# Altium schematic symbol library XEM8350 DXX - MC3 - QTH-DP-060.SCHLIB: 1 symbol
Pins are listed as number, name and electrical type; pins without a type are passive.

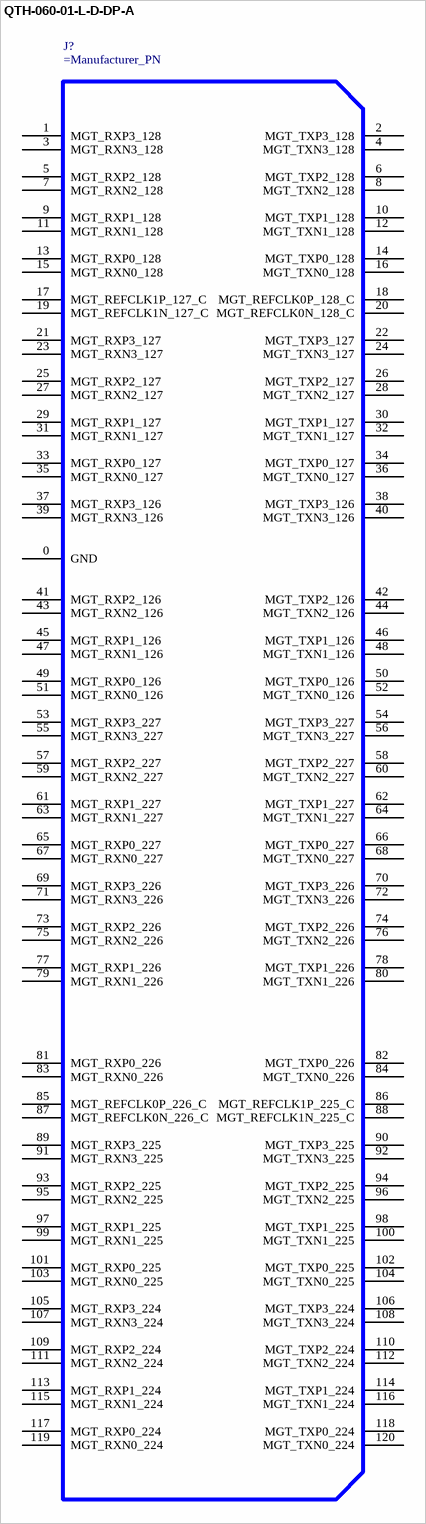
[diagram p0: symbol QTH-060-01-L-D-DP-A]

## QTH-060-01-L-D-DP-A
designator J?
pins: 0 GND, 1 MGT_RXP3_128, 2 MGT_TXP3_128, 3 MGT_RXN3_128, 4 MGT_TXN3_128, 5 MGT_RXP2_128, 6 MGT_TXP2_128, 7 MGT_RXN2_128, 8 MGT_TXN2_128, 9 MGT_RXP1_128, 10 MGT_TXP1_128, 11 MGT_RXN1_128, 12 MGT_TXN1_128, 13 MGT_RXP0_128, 14 MGT_TXP0_128, 15 MGT_RXN0_128, 16 MGT_TXN0_128, 17 MGT_REFCLK1P_127_C, 18 MGT_REFCLK0P_128_C, 19 MGT_REFCLK1N_127_C, 20 MGT_REFCLK0N_128_C, 21 MGT_RXP3_127, 22 MGT_TXP3_127, 23 MGT_RXN3_127, 24 MGT_TXN3_127, 25 MGT_RXP2_127, 26 MGT_TXP2_127, 27 MGT_RXN2_127, 28 MGT_TXN2_127, 29 MGT_RXP1_127, 30 MGT_TXP1_127, 31 MGT_RXN1_127, 32 MGT_TXN1_127, 33 MGT_RXP0_127, 34 MGT_TXP0_127, 35 MGT_RXN0_127, 36 MGT_TXN0_127, 37 MGT_RXP3_126, 38 MGT_TXP3_126, 39 MGT_RXN3_126, 40 MGT_TXN3_126, 41 MGT_RXP2_126, 42 MGT_TXP2_126, 43 MGT_RXN2_126, 44 MGT_TXN2_126, 45 MGT_RXP1_126, 46 MGT_TXP1_126, 47 MGT_RXN1_126, 48 MGT_TXN1_126, 49 MGT_RXP0_126, 50 MGT_TXP0_126, 51 MGT_RXN0_126, 52 MGT_TXN0_126, 53 MGT_RXP3_227, 54 MGT_TXP3_227, 55 MGT_RXN3_227, 56 MGT_TXN3_227, 57 MGT_RXP2_227, 58 MGT_TXP2_227, 59 MGT_RXN2_227, 60 MGT_TXN2_227, 61 MGT_RXP1_227, 62 MGT_TXP1_227, 63 MGT_RXN1_227, 64 MGT_TXN1_227, 65 MGT_RXP0_227, 66 MGT_TXP0_227, 67 MGT_RXN0_227, 68 MGT_TXN0_227, 69 MGT_RXP3_226, 70 MGT_TXP3_226, 71 MGT_RXN3_226, 72 MGT_TXN3_226, 73 MGT_RXP2_226, 74 MGT_TXP2_226, 75 MGT_RXN2_226, 76 MGT_TXN2_226, 77 MGT_RXP1_226, 78 MGT_TXP1_226, 79 MGT_RXN1_226, 80 MGT_TXN1_226, 81 MGT_RXP0_226, 82 MGT_TXP0_226, 83 MGT_RXN0_226, 84 MGT_TXN0_226, 85 MGT_REFCLK0P_226_C, 86 MGT_REFCLK1P_225_C, 87 MGT_REFCLK0N_226_C, 88 MGT_REFCLK1N_225_C, 89 MGT_RXP3_225, 90 MGT_TXP3_225, 91 MGT_RXN3_225, 92 MGT_TXN3_225, 93 MGT_RXP2_225, 94 MGT_TXP2_225, 95 MGT_RXN2_225, 96 MGT_TXN2_225, 97 MGT_RXP1_225, 98 MGT_TXP1_225, 99 MGT_RXN1_225, 100 MGT_TXN1_225, 101 MGT_RXP0_225, 102 MGT_TXP0_225, 103 MGT_RXN0_225, 104 MGT_TXN0_225, 105 MGT_RXP3_224, 106 MGT_TXP3_224, 107 MGT_RXN3_224, 108 MGT_TXN3_224, 109 MGT_RXP2_224, 110 MGT_TXP2_224, 111 MGT_RXN2_224, 112 MGT_TXN2_224, 113 MGT_RXP1_224, 114 MGT_TXP1_224, 115 MGT_RXN1_224, 116 MGT_TXN1_224, 117 MGT_RXP0_224, 118 MGT_TXP0_224, 119 MGT_RXN0_224, 120 MGT_TXN0_224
